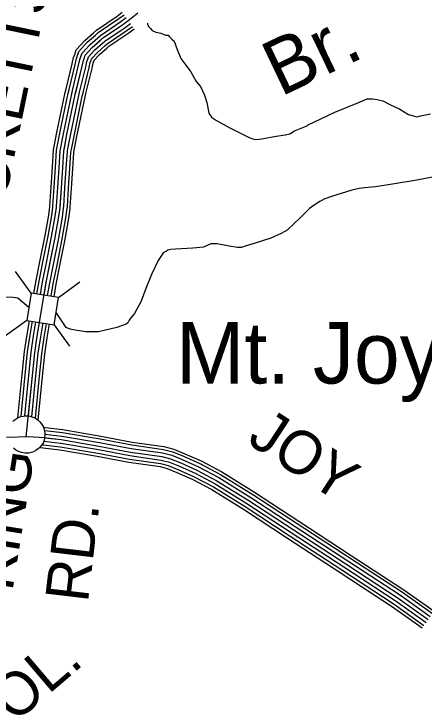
# Model space of a CAD drawing. Extents: x 1551132 to 1791609, y 378168 to 563823.
# Drawn here: x 1592970 to 1596494, y 433719 to 439720 of the extents above; entities that cross this region are included whole.
import ezdxf

# ---------------------------------------------------------------- set-up
doc = ezdxf.new("R2010")
doc.units = 0
for name, color, linetype in [('DESIGN - DRAINAGE - Bridges and Cross Drains Size Text', 7, 'Continuous'), ('DESIGN - ROW - Right-of-Way and Easement Labels', 7, 'Continuous'), ('DESIGN - TRANSPORTATION - Text', 7, 'Continuous'), ('SURVEY - CONTOURS - Index with Text', 7, 'Continuous'), ('SURVEY - DRAINAGE - Storm Sewer', 7, 'Continuous'), ('SURVEY - TRANSPORTATION - Roads', 7, 'Continuous'), ('SURVEY - VEGETATION - Features with Text', 7, 'Continuous')]:
    doc.layers.add(name, color=color, linetype=linetype)

msp = doc.modelspace()

# ---------------------------------------------------------------- linework, layer by layer
at = {"layer": 'DESIGN - TRANSPORTATION - Text'}
for points in [[(1594118.31, 439640.778), (1594116.544, 439634.761), (1594126.352, 439612.66), (1594144.185, 439594.485), (1594158.043, 439578.351), (1594189.9, 439564.059), (1594231.799, 439555.676), (1594271.64, 439539.309), (1594295.615, 439539.092), (1594307.489, 439524.975), (1594325.314, 439504.799), (1594345.147, 439486.616), (1594372.538, 439416.322), (1594403.862, 439337.987), (1594488.843, 439223.15), (1594536.125, 439140.673), (1594573.733, 439096.305), (1594607.082, 439021.962), (1594626.556, 438959.744), (1594640.039, 438899.584), (1594643.789, 438869.533), (1594651.664, 438855.449), (1594657.597, 438847.391), (1594667.472, 438833.29), (1594711.204, 438804.881), (1594818.635, 438745.88), (1594991.798, 438660.269), (1595023.672, 438647.977), (1595045.621, 438643.777), (1595099.629, 438649.302), (1595223.734, 438672.203), (1595299.757, 438681.528), (1595341.815, 438691.154), (1595381.997, 438716.813), (1595494.294, 438761.839), (1595492.328, 438765.856), (1595727.097, 438877.825), (1595925.626, 438958.094), (1596003.849, 438991.42), (1596051.815, 438990.987), (1596089.756, 438986.645), (1596139.613, 438974.187), (1596199.32, 438943.636), (1596286.918, 438902.826), (1596360.491, 438858.134), (1596392.382, 438847.842), (1596432.272, 438837.475), (1596464.313, 438845.192), (1596550.395, 438862.434)], [(1596565.861, 438319.936), (1596431.73, 438293.127), (1596239.593, 438260.826), (1596077.497, 438236.259), (1595981.491, 438227.117), (1595935.475, 438221.525), (1595873.41, 438208.075), (1595699.072, 438153.598), (1595640.94, 438132.106), (1595598.783, 438110.472), (1595550.559, 438078.879), (1595508.335, 438049.237), (1595427.704, 437965.91), (1595377.355, 437920.325), (1595316.915, 437862.832), (1595266.724, 437835.265), (1595178.459, 437796.03), (1595042.179, 437751.221), (1594956.048, 437727.978), (1594925.949, 437714.236), (1594891.991, 437716.545), (1594820.134, 437727.195), (1594716.362, 437746.137), (1594704.387, 437748.245), (1594660.405, 437746.645), (1594598.223, 437719.178), (1594508.208, 437709.986), (1594358.237, 437701.319), (1594318.238, 437697.677), (1594292.205, 437691.91), (1594278.139, 437682.027), (1594254.073, 437672.235), (1594209.54, 437604.591), (1594152.583, 437485.021), (1594101.601, 437363.401), (1594062.727, 437255.674), (1594005.887, 437150.112), (1593973.579, 437110.378), (1593959.421, 437090.494), (1593947.246, 437068.585), (1593933.163, 437056.71), (1593854.973, 437027.384), (1593694.777, 436990.8), (1593586.863, 436991.766), (1593497.032, 437004.583), (1593453.133, 437012.984), (1593417.275, 437027.309), (1593331.436, 437157.012), (1593331.252, 437155.696)], [(1593098.308, 437200.53), (1593097.708, 437200.188), (1593001.668, 437279.207), (1592961.769, 437287.565), (1592899.829, 437290.124), (1592739.858, 437279.548), (1592639.785, 437262.44), (1592591.72, 437250.856), (1592511.397, 437205.546), (1592459.039, 437157.987), (1592389.241, 437003.466)]]:
    msp.add_lwpolyline(points, dxfattribs=at)
at = {"layer": 'SURVEY - CONTOURS - Index with Text'}
for points in [[(1593224.104, 436170.103), (1593236.846, 436169.236), (1593388.95, 436151.603), (1593715.701, 436096.56), (1593986.161, 436044.659), (1594258.305, 436006.224), (1594342.936, 435984.932), (1594437.542, 435945.348), (1594578.622, 435882.646), (1594757.193, 435788.436), (1595035.436, 435615.94), (1595416.394, 435366.183), (1595868.217, 435072.351), (1596321.522, 434775.535), (1596579.525, 434592.372)], [(1593231.087, 436144.861), (1593234.579, 436144.619), (1593385.475, 436127.119), (1593711.318, 436072.234), (1593982.103, 436020.266), (1594253.547, 435981.94), (1594335.111, 435961.415), (1594427.751, 435922.647), (1594567.823, 435860.396), (1594744.902, 435766.977), (1595022.145, 435595.097), (1595402.886, 435345.491), (1595854.709, 435051.65), (1596307.598, 434755.11), (1596565.217, 434572.222)], [(1592906.97, 436087.276), (1593096.974, 436091.859), (1593228.896, 436082.859), (1593376.751, 436065.717), (1593700.326, 436011.207), (1593971.92, 435959.09), (1594241.614, 435921.005), (1594315.47, 435902.422), (1594403.193, 435865.712), (1594540.74, 435804.586), (1594714.069, 435713.142), (1594988.812, 435542.813), (1595368.987, 435293.573), (1595820.826, 434999.724), (1596272.657, 434703.875), (1596529.326, 434521.662)], [(1593233.179, 436082.359), (1593376.751, 436065.717), (1593700.326, 436011.207), (1593971.92, 435959.09), (1594241.614, 435921.005), (1594315.47, 435902.422), (1594403.193, 435865.712), (1594540.74, 435804.586), (1594714.069, 435713.142), (1594988.812, 435542.813), (1595368.987, 435293.573), (1595820.826, 434999.724), (1596272.657, 434703.875), (1596529.326, 434521.662)], [(1593234.837, 436113.377), (1593381.117, 436096.418), (1593705.826, 436041.717), (1593977.011, 435989.682), (1594247.58, 435951.473), (1594325.287, 435931.914), (1594415.468, 435894.18), (1594554.281, 435832.495), (1594729.485, 435740.059), (1595005.479, 435568.955), (1595385.936, 435319.532), (1595837.767, 435025.683), (1596290.123, 434729.492), (1596547.267, 434546.938)], [(1593212.229, 436021.849), (1593223.212, 436021.099), (1593368.026, 436004.315), (1593689.335, 435950.181), (1593961.737, 435897.913), (1594229.68, 435860.071), (1594295.829, 435843.428), (1594378.635, 435808.778), (1594513.657, 435748.776), (1594683.236, 435659.307), (1594955.48, 435490.528), (1595335.087, 435241.655), (1595786.943, 434947.798), (1596237.716, 434652.64), (1596493.435, 434471.102)], [(1593225.854, 436052), (1593226.054, 436051.983), (1593372.384, 436035.016), (1593694.826, 435980.698), (1593966.828, 435928.497), (1594235.647, 435890.538), (1594305.654, 435872.929), (1594390.918, 435837.245), (1594527.198, 435776.677), (1594698.653, 435686.225), (1594972.146, 435516.67), (1595352.037, 435267.614), (1595803.885, 434973.765), (1596255.191, 434678.258), (1596511.384, 434496.386)], [(1593189.605, 435997.615), (1593220.854, 435995.482), (1593364.409, 435978.84), (1593684.777, 435924.872), (1593957.512, 435872.537), (1594224.731, 435834.803), (1594287.687, 435818.961), (1594368.452, 435785.16), (1594502.424, 435725.625), (1594670.445, 435636.982), (1594941.655, 435468.844), (1595321.029, 435220.121), (1595772.894, 434926.264), (1596223.225, 434631.39), (1596478.552, 434450.135)]]:
    msp.add_lwpolyline(points, dxfattribs=at)
at = {"layer": 'SURVEY - DRAINAGE - Storm Sewer'}
for p, q in [((1593117.376, 437324.427), (1592983.872, 437508.175)), ((1593352.07, 437287.258), (1593535.808, 437420.771)), ((1593080.224, 437089.751), (1592896.477, 436956.238)), ((1593314.85, 437052.59), (1593448.363, 436868.843))]:
    msp.add_line(p, q, dxfattribs=at)
msp.add_lwpolyline([(1593080.224, 437089.751), (1593314.892, 437052.582), (1593352.07, 437287.258), (1593117.376, 437324.427)], close=True, dxfattribs=at)
at = {"layer": 'SURVEY - TRANSPORTATION - Roads'}
for points in [[(1593075.591, 436091.342), (1593147.665, 436811.586), (1593168.831, 436953.49), (1593246.63, 437415.094), (1593323.811, 437802.662), (1593355.269, 437980.492), (1593365.902, 438056.452), (1593377.327, 438228.457), (1593388.735, 438398.47), (1593397.935, 438542.482), (1593425.093, 438684.336), (1593495.916, 439027.928), (1593555.923, 439273.551), (1593566.315, 439321.486), (1593574.49, 439343.428), (1593582.681, 439367.37), (1593642.78, 439433.572), (1593731.786, 439512.132), (1593906.657, 439630.636), (1593962.964, 439672.162), (1594035.387, 439729.547)], [(1593651.988, 439558.709), (1593677.946, 439581.609), (1593856.008, 439702.271), (1593900.407, 439735.013)], [(1593669.004, 439539.425), (1593693.729, 439561.242), (1593870.858, 439681.27), (1593915.532, 439714.213)], [(1593689.52, 439516.174), (1593712.762, 439536.683), (1593888.758, 439655.953), (1593933.773, 439689.154)], [(1593710.028, 439492.932), (1593731.786, 439512.132), (1593906.657, 439630.636), (1593951.981, 439664.062)], [(1593730.536, 439469.69), (1593750.811, 439487.582), (1593924.557, 439605.318), (1593970.197, 439638.969)], [(1593751.052, 439446.439), (1593769.844, 439463.023), (1593942.456, 439580.001), (1593988.414, 439613.902)], [(1593417.768, 439077.638), (1593470.442, 439293.26), (1593481.925, 439346.22), (1593491.883, 439372.945), (1593505.558, 439412.913), (1593581.098, 439496.132), (1593652.005, 439558.709)], [(1593767.402, 439427.905), (1593785.01, 439443.447), (1593956.731, 439559.817), (1594002.938, 439593.893)], [(1593442.751, 439071.537), (1593495.508, 439287.476), (1593506.666, 439338.969), (1593516.099, 439364.287), (1593528.166, 439399.563), (1593599.181, 439477.79), (1593669.021, 439539.425)], [(1593472.859, 439064.179), (1593525.716, 439280.518), (1593536.491, 439330.228), (1593545.299, 439353.862), (1593555.424, 439383.462), (1593620.98, 439455.681), (1593689.529, 439516.183)], [(1593502.975, 439056.82), (1593555.923, 439273.551), (1593566.315, 439321.486), (1593574.49, 439343.428), (1593582.681, 439367.37), (1593642.78, 439433.572), (1593710.045, 439492.94)], [(1593533.09, 439049.462), (1593586.131, 439266.584), (1593596.139, 439312.744), (1593603.681, 439332.994), (1593609.939, 439351.278), (1593664.579, 439411.463), (1593730.561, 439469.698)], [(1593563.198, 439042.103), (1593616.339, 439259.626), (1593625.963, 439304.002), (1593632.88, 439322.569), (1593637.197, 439335.178), (1593686.379, 439389.354), (1593751.069, 439446.456)], [(1593587.214, 439036.237), (1593640.43, 439254.067), (1593649.746, 439297.035), (1593656.154, 439314.244), (1593658.929, 439322.344), (1593703.753, 439371.729), (1593767.427, 439427.922)], [(1593316.487, 438583.516), (1593339.061, 438701.436), (1593410.327, 439047.195), (1593417.768, 439077.638)], [(1593341.745, 438578.683), (1593364.286, 438696.428), (1593435.418, 439041.545), (1593442.743, 439071.537)], [(1593372.186, 438572.849), (1593394.685, 438690.377), (1593465.667, 439034.736), (1593472.859, 439064.187)], [(1593402.635, 438567.024), (1593425.093, 438684.336), (1593495.916, 439027.928), (1593502.975, 439056.829)], [(1593433.084, 438561.199), (1593455.5, 438678.294), (1593526.166, 439021.119), (1593533.09, 439049.47)], [(1593463.525, 438555.366), (1593485.9, 438672.244), (1593556.415, 439014.311), (1593563.206, 439042.12)], [(1593487.8, 438550.715), (1593510.149, 438667.427), (1593580.531, 439008.878), (1593587.214, 439036.253)], [(1593279.179, 438074.32), (1593289.804, 438234.299), (1593301.204, 438404.203), (1593310.754, 438553.565), (1593316.487, 438583.533)], [(1593304.837, 438072.611), (1593315.47, 438232.59), (1593326.87, 438402.52), (1593336.311, 438550.315), (1593341.745, 438578.691)], [(1593335.769, 438070.561), (1593346.394, 438230.524), (1593357.803, 438400.495), (1593367.119, 438546.399), (1593372.186, 438572.866)], [(1593366.702, 438068.503), (1593377.327, 438228.457), (1593388.735, 438398.47), (1593397.935, 438542.482), (1593402.635, 438567.041)], [(1593397.635, 438066.444), (1593408.26, 438226.39), (1593419.668, 438396.445), (1593428.751, 438538.565), (1593433.084, 438561.216)], [(1593428.567, 438064.394), (1593439.184, 438224.324), (1593450.6, 438394.42), (1593459.559, 438534.648), (1593463.525, 438555.391)], [(1593453.225, 438062.753), (1593463.85, 438222.682), (1593475.266, 438392.803), (1593484.125, 438531.523), (1593487.808, 438550.74)], [(1593192.748, 437593.607), (1593237.605, 437818.871), (1593268.621, 437994.217), (1593278.588, 438065.444), (1593279.179, 438074.32)], [(1593217.964, 437588.582), (1593262.879, 437814.121), (1593294.02, 437990.192), (1593304.187, 438062.811), (1593304.837, 438072.62)], [(1593248.371, 437582.532), (1593293.345, 437808.388), (1593324.645, 437985.342), (1593335.045, 438059.628), (1593335.769, 438070.569)], [(1593278.771, 437576.473), (1593323.811, 437802.662), (1593355.269, 437980.492), (1593365.902, 438056.452), (1593366.702, 438068.519)], [(1593309.17, 437570.415), (1593354.277, 437796.937), (1593385.893, 437975.642), (1593396.76, 438053.277), (1593397.635, 438066.469)], [(1593339.577, 437564.365), (1593384.743, 437791.204), (1593416.518, 437970.792), (1593427.617, 438050.094), (1593428.567, 438064.419)], [(1593363.819, 437559.539), (1593409.034, 437786.637), (1593440.934, 437966.925), (1593452.217, 438047.561), (1593453.225, 438062.786)], [(1593141.74, 437320.525), (1593160.348, 437430.953), (1593192.748, 437593.624)], [(1593167.148, 437316.541), (1593185.648, 437426.303), (1593217.964, 437588.598)], [(1593197.764, 437311.675), (1593216.139, 437420.702), (1593248.371, 437582.548)], [(1593228.388, 437306.866), (1593246.63, 437415.094), (1593278.771, 437576.49)], [(1593259.004, 437302.008), (1593277.12, 437409.485), (1593309.17, 437570.431)], [(1593289.628, 437297.191), (1593307.611, 437403.885), (1593339.577, 437564.381)], [(1593314.045, 437293.307), (1593331.927, 437399.419), (1593363.819, 437559.556)], [(1593038.092, 436597.581), (1593060.6, 436822.428), (1593082.2, 436967.249), (1593102.249, 437086.252)], [(1593063.683, 436595.022), (1593086.125, 436819.253), (1593107.599, 436963.215), (1593127.649, 437082.227)], [(1593094.524, 436591.931), (1593116.89, 436815.42), (1593138.215, 436958.357), (1593158.273, 437077.385)], [(1593125.373, 436588.847), (1593147.665, 436811.586), (1593168.831, 436953.49), (1593188.889, 437072.535)], [(1593156.223, 436585.764), (1593178.439, 436807.753), (1593199.447, 436948.623), (1593219.505, 437067.676)], [(1593187.064, 436582.672), (1593209.205, 436803.92), (1593230.063, 436943.765), (1593250.129, 437062.826)], [(1593211.655, 436580.214), (1593233.738, 436800.861), (1593254.479, 436939.89), (1593274.537, 437058.96)], [(1593003.601, 436252.905), (1593038.092, 436597.597)], [(1593030.7, 436265.38), (1593063.683, 436595.039)], [(1593062.383, 436270.689), (1593094.524, 436591.947)], [(1593093.407, 436269.364), (1593125.373, 436588.864)], [(1593123.865, 436262.397), (1593156.223, 436585.78)], [(1593153.839, 436250.655), (1593187.064, 436582.689)], [(1593177.03, 436234.205), (1593211.655, 436580.23)]]:
    msp.add_lwpolyline(points, dxfattribs=at)
at = {"layer": 'SURVEY - VEGETATION - Features with Text'}
msp.add_lwpolyline([(1592958.727, 436220.846), (1592972.527, 436234.138), (1592988.526, 436244.821), (1593006.493, 436254.922), (1593029.501, 436264.264), (1593051.625, 436268.472), (1593069.483, 436270.414), (1593096.599, 436269.072), (1593115.449, 436265.105), (1593130.648, 436259.739), (1593148.531, 436252.088), (1593163.164, 436244.055), (1593178.739, 436233.063), (1593193.13, 436219.304), (1593204.388, 436204.504), (1593213.838, 436188.545), (1593223.329, 436172.545), (1593229.954, 436151.861), (1593234.429, 436124.677), (1593235.096, 436105.501), (1593233.421, 436084.042), (1593227.879, 436061.175), (1593222.338, 436041.041), (1593210.229, 436022.124), (1593195.438, 436002.982), (1593177.964, 435987.798), (1593156.497, 435972.123), (1593136.698, 435961.664), (1593117.332, 435955.264), (1593096.324, 435950.605), (1593063.725, 435949.689), (1593035.025, 435954.631), (1593009.526, 435963.781), (1592985.36, 435976.231), (1592965.102, 435991.548)], dxfattribs=at)

# ---------------------------------------------------------------- texts
at = {"layer": 'DESIGN - DRAINAGE - Bridges and Cross Drains Size Text'}
msp.add_text('Br.', height=474.9935, rotation=25.4980917, dxfattribs=at).set_placement((1595259.983, 439006.254))
at = {"layer": 'DESIGN - ROW - Right-of-Way and Easement Labels'}
for s, height, rotation, p in [('RICKETTS', 370.009, 78.353725, (1592793.115, 437622.949)), ('JOY', 369.9966, 326.7510972, (1594961.922, 436043.192)), ('KING', 370.0093, 80.9144444, (1592955.901, 434757.716)), ('RD.', 370.0095, 83.2827861, (1593604.844, 434660.547)), ('HOL.', 369.9993, 40.4553194, (1592700.99, 433393.072))]:
    msp.add_text(s, height=height, rotation=rotation, dxfattribs=at).set_placement(p)
at = {"layer": 'SURVEY - VEGETATION - Features with Text'}
msp.add_text('Mt. Joy', height=527.9876, rotation=0.0000361, dxfattribs=at).set_placement((1594362.211, 436547.589))

doc.saveas('drawing.dxf')
